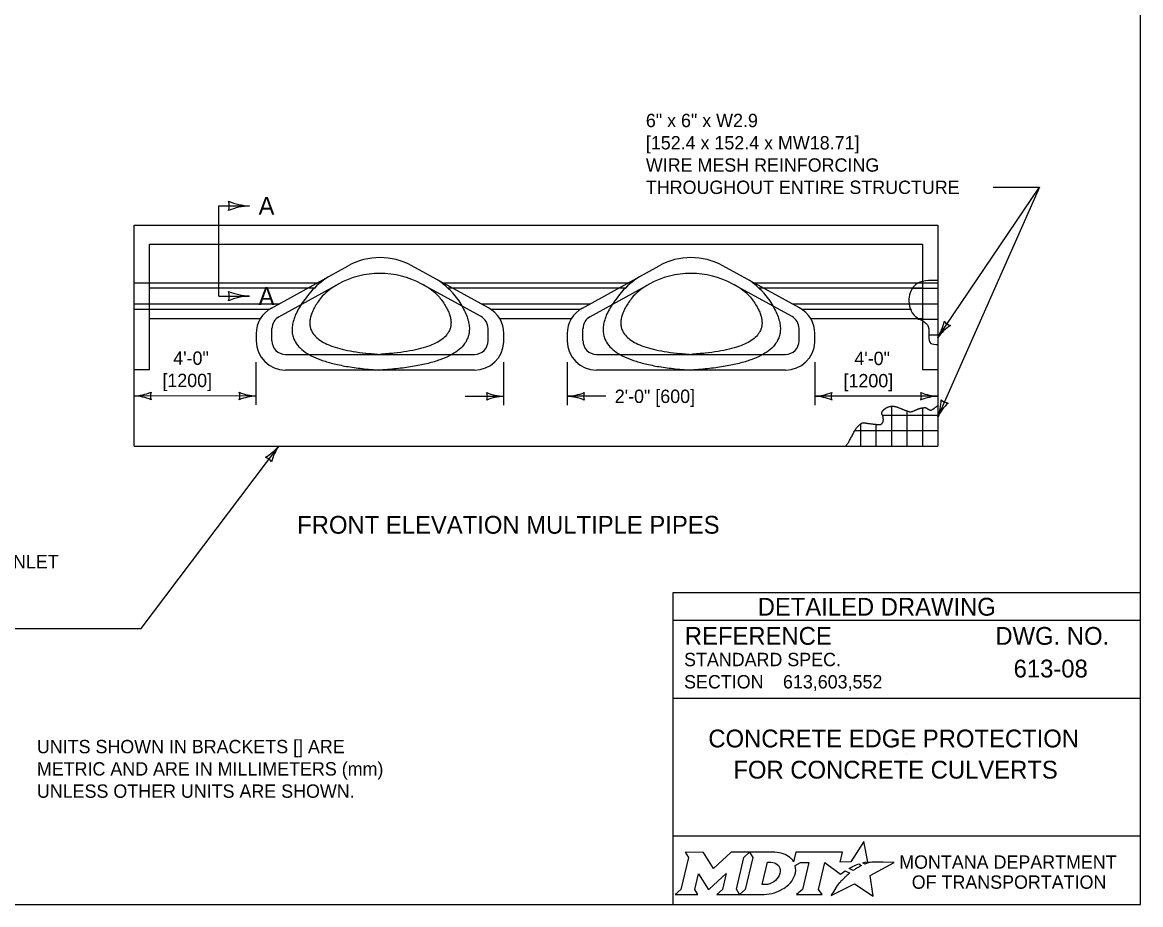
# Model space of a CAD drawing. Extents: x 49991.4 to 50021, y 49987.6 to 50011.4.
# Drawn here: x 50015.92 to 50020.94, y 49999.89 to 50003.85 of the extents above; entities that cross this region are included whole.
import ezdxf

# ---------------------------------------------------------------- set-up
doc = ezdxf.new("R2010")
doc.units = 0
for name, color, linetype in [('Default', 7, 'Continuous'), ('Level 1', 7, 'Continuous'), ('Level 2', 7, 'Continuous'), ('Level 3', 7, 'Continuous'), ('Level 4', 7, 'Continuous'), ('Level 6', 7, 'Continuous')]:
    doc.layers.add(name, color=color, linetype=linetype)

msp = doc.modelspace()

# ---------------------------------------------------------------- linework, layer by layer
at = {"layer": 'Default'}
for points in [[(50019.7003, 50000.0679), (50019.69, 50000.0735), (50019.7016, 50000.0763), (50019.7132, 50000.0783), (50019.6958, 50000.1684), (50019.6363, 50000.0771), (50019.589, 50000.0764), (50019.5993, 50000.1205), (50019.3901, 50000.1206), (50019.38, 50000.0781), (50019.3742, 50000.0864)], [(50018.8933, 50000.1206), (50018.9074, 50000.0972), (50018.8739, 49999.9539), (50018.8482, 49999.9314), (50018.9498, 49999.9314), (50018.9363, 49999.9542), (50018.9525, 50000.0243), (50018.9962, 49999.9553), (50019.0015, 49999.9553), (50019.0766, 50000.0248), (50019.0602, 49999.9537), (50019.0355, 49999.9317), (50019.1371, 49999.9317), (50019.1233, 49999.955), (50019.1565, 50000.0974)], [(50019.1565, 50000.0974), (50019.1818, 50000.1206), (50019.0994, 50000.1206), (50019.0198, 50000.0476), (50018.9753, 50000.1203), (50018.8933, 50000.1206)], [(50019.2954, 50000.1206), (50019.1818, 50000.1206), (50019.1965, 50000.0977), (50019.1626, 49999.9539), (50019.1371, 49999.9317), (50019.2477, 49999.9317)], [(50019.3194, 50000.0339), (50019.3182, 50000.0258), (50019.315, 50000.0165), (50019.3108, 50000.0083), (50019.3052, 50000.0008), (50019.2987, 49999.9939), (50019.2908, 49999.9876), (50019.2825, 49999.9829), (50019.2734, 49999.979), (50019.2643, 49999.9767), (50019.2551, 49999.9758), (50019.2392, 49999.9758), (50019.2628, 50000.0758), (50019.2788, 50000.0758), (50019.2864, 50000.0752), (50019.294, 50000.0733), (50019.3006, 50000.0703), (50019.3067, 50000.0661), (50019.3115, 50000.0611), (50019.3152, 50000.0551), (50019.3179, 50000.0489), (50019.3195, 50000.0415), (50019.3195, 50000.0385), (50019.3194, 50000.0339)], [(50019.3868, 50000.0615), (50019.4114, 50000.0746), (50019.4483, 50000.0746), (50019.4197, 49999.9541), (50019.3922, 49999.9314), (50019.5084, 49999.9314), (50019.4914, 49999.9543), (50019.5196, 50000.0745), (50019.5909, 50000.0228), (50019.612, 50000.0379), (50019.6317, 50000.027)], [(50019.5759, 49999.9711), (50019.5606, 49999.9467), (50019.5559, 49999.9392), (50019.5501, 49999.9306), (50019.5478, 49999.9263), (50019.6531, 49999.9794), (50019.737, 49999.9243), (50019.7239, 50000.017), (50019.8308, 50000.0754), (50019.7815, 50000.0762), (50019.7514, 50000.0766), (50019.7306, 50000.0769), (50019.7238, 50000.0754), (50019.7189, 50000.0742), (50019.7105, 50000.0719), (50019.7003, 50000.0679)], [(50019.6499, 50000.0403), (50019.6475, 50000.0386), (50019.6292, 50000.0482), (50019.6395, 50000.0539), (50019.6436, 50000.0561), (50019.6522, 50000.0601), (50019.6579, 50000.0627), (50019.6658, 50000.0657), (50019.6731, 50000.0684), (50019.6849, 50000.061), (50019.6809, 50000.0589), (50019.6763, 50000.0564), (50019.6721, 50000.0542), (50019.6671, 50000.0513), (50019.6652, 50000.0502), (50019.6625, 50000.0486), (50019.66, 50000.0472), (50019.6577, 50000.0456), (50019.6551, 50000.0438), (50019.6524, 50000.042), (50019.6499, 50000.0403)], [(50019.5898, 49999.9872), (50019.5898, 49999.9872)], [(50019.2934, 49999.939), (50019.3018, 49999.9416), (50019.3148, 49999.947), (50019.3352, 49999.958)]]:
    msp.add_lwpolyline(points, dxfattribs=at)
for centre, radius, start, end in [((50019.2745, 50000.0595), 0.1183, 300.9103, 339.1383), ((50019.3185, 50000.0422), 0.0709, 339.5329, 15.8582)]:
    msp.add_arc(centre, radius, start, end, dxfattribs=at)
for centre, major_axis, ratio, start_param, end_param in [((50019.2933, 50000.0732), (0.0834, -0.0037), 0.568097, 0.61298, 1.570796), ((50019.3489, 50000.0805), (0.0361, -0.0295), 0.469099, 1.225588, 1.570796), ((50019.6206, 50000.0173), (-0.0112, -0.0097), 0.021651, 3.157348, 6.283185), ((50019.5829, 49999.9791), (-0.00694, -0.00806), 0.008222, 0, 3.137361), ((50019.5996, 49999.9974), (-0.0098, -0.0102), 0.016458, 3.141593, 6.279097), ((50019.248, 50000.08), (0, 0.1484), 0.987302, 3.139398, 3.456847)]:
    msp.add_ellipse(centre, major_axis=major_axis, ratio=ratio, start_param=start_param, end_param=end_param, dxfattribs=at)
at = {"layer": 'Level 1'}
for p, q in [((50016.4192, 50002.9359), (50020.0271, 50002.9359)), ((50016.4192, 50001.9446), (50016.4192, 50002.9359)), ((50020.0271, 50002.9359), (50020.0271, 50001.9446)), ((50017.0353, 50002.564), (50017.3799, 50002.7539)), ((50018.0107, 50002.5649), (50017.6657, 50002.7541)), ((50018.4316, 50002.564), (50018.7762, 50002.7539)), ((50019.407, 50002.5649), (50019.062, 50002.7541)), ((50019.9578, 50002.6833), (50019.9578, 50002.5007)), ((50017.0694, 50002.5252), (50017.335, 50002.6714)), ((50017.9766, 50002.5258), (50017.7105, 50002.6718)), ((50018.4657, 50002.5252), (50018.7313, 50002.6714)), ((50019.3729, 50002.5258), (50019.1068, 50002.6718)), ((50019.9159, 50002.6527), (50020.0271, 50002.6527)), ((50016.4192, 50002.5833), (50017.0703, 50002.5833)), ((50017.9771, 50002.5833), (50018.4666, 50002.5833)), ((50019.3734, 50002.5833), (50020.0271, 50002.5833)), ((50016.4192, 50002.5586), (50017.0263, 50002.5586)), ((50018.021, 50002.5586), (50018.4226, 50002.5586)), ((50019.4173, 50002.5586), (50019.9091, 50002.5586)), ((50019.9381, 50002.5139), (50020.0271, 50002.5139)), ((50016.9672, 50002.4488), (50016.9672, 50002.4169)), ((50017.038, 50002.4169), (50017.038, 50002.472)), ((50018.0081, 50002.4169), (50018.0081, 50002.4727)), ((50018.0788, 50002.4114), (50018.0789, 50002.4496)), ((50018.3635, 50002.4488), (50018.3635, 50002.4169)), ((50018.4343, 50002.4169), (50018.4343, 50002.472)), ((50019.4044, 50002.4169), (50019.4044, 50002.4727)), ((50019.4751, 50002.4114), (50019.4752, 50002.4496)), ((50019.9872, 50002.4445), (50020.0271, 50002.4445)), ((50017.0987, 50002.3562), (50017.9474, 50002.3562)), ((50018.495, 50002.3562), (50019.3437, 50002.3562)), ((50017.9474, 50002.2854), (50017.0987, 50002.2854)), ((50019.3437, 50002.2854), (50018.495, 50002.2854)), ((50019.819, 50002.1233), (50019.819, 50001.9446)), ((50019.7784, 50002.0834), (50020.0271, 50002.0834)), ((50019.8884, 50002.1027), (50019.8884, 50001.9446)), ((50019.9578, 50002.116), (50019.9578, 50001.9446)), ((50019.6802, 50002.0435), (50019.6802, 50001.9446)), ((50019.7496, 50002.0421), (50019.7496, 50001.9446)), ((50019.6548, 50002.014), (50020.0271, 50002.014)), ((50016.4192, 50001.9446), (50020.0271, 50001.9446))]:
    msp.add_line(p, q, dxfattribs=at)
msp.add_lwpolyline([(50020.9378, 50008.1646), (50009.7374, 50008.1646), (50009.7374, 49999.8856), (50020.9378, 49999.8856)], close=True, dxfattribs=at)
for centre, major_axis, start_param, end_param in [((50017.523, 50002.494), (0, 0.2967), 5.781332, 6.786673), ((50018.9193, 50002.494), (0, 0.2967), 5.781332, 6.786673), ((50017.523, 50002.3301), (0, 0.3897), 5.781311, 6.786734), ((50018.9193, 50002.3301), (0, 0.3897), 5.781311, 6.786734), ((50017.4619, 50002.4312), (0, 0.2717), 0.485979, 0.816691), ((50017.5916, 50002.4272), (0, 0.2717), 5.466495, 5.799741), ((50018.8582, 50002.4312), (0, 0.2717), 0.485979, 0.816691), ((50018.9879, 50002.4272), (0, 0.2717), 5.466495, 5.799741), ((50017.0987, 50002.4488), (0, 0.1315), 0.503156, 1.570796), ((50017.0987, 50002.472), (0, 0.0606), 0.503453, 1.570796), ((50017.9474, 50002.4727), (0, 0.0606), 4.712389, 5.781265), ((50017.9474, 50002.4496), (0, 0.1315), 4.712389, 5.781202), ((50018.495, 50002.4488), (0, 0.1315), 0.503156, 1.570796), ((50018.495, 50002.472), (0, 0.0606), 0.503453, 1.570796), ((50019.3437, 50002.4727), (0, 0.0606), 4.712389, 5.781265), ((50019.3437, 50002.4496), (0, 0.1315), 4.712389, 5.781202), ((50017.0987, 50002.4169), (0, -0.1315), 4.712389, 6.283185), ((50017.0987, 50002.4169), (0, -0.0606), 4.712389, 6.283185), ((50017.9474, 50002.4169), (0, -0.0606), 0, 1.570796), ((50017.9474, 50002.4169), (0, -0.1315), 0, 1.528873), ((50018.495, 50002.4169), (0, -0.1315), 4.712389, 6.283185), ((50018.495, 50002.4169), (0, -0.0606), 4.712389, 6.283185), ((50019.3437, 50002.4169), (0, -0.0606), 0, 1.570796), ((50019.3437, 50002.4169), (0, -0.1315), 0, 1.528873)]:
    msp.add_ellipse(centre, major_axis=major_axis, ratio=0.999965, start_param=start_param, end_param=end_param, dxfattribs=at)
msp.add_spline([(50020.0271, 50002.6879), (50019.9266, 50002.6683), (50019.8977, 50002.6046), (50019.9266, 50002.5268), (50019.9845, 50002.4806), (50019.9961, 50002.4056), (50020.0271, 50002.4005)], degree=3, dxfattribs=at)
for points, degree in [([(50017.2638, 50002.6173), (50017.0752, 50002.3841), (50017.523, 50002.3562)], 2), ([(50017.7896, 50002.6132), (50017.9707, 50002.384), (50017.523, 50002.3562)], 2), ([(50018.6601, 50002.6173), (50018.4715, 50002.3841), (50018.9193, 50002.3562)], 2), ([(50019.1859, 50002.6132), (50019.367, 50002.384), (50018.9193, 50002.3562)], 2), ([(50019.6132, 50001.9446), (50019.6163, 50001.9477), (50019.6191, 50001.9512), (50019.6218, 50001.9547), (50019.6246, 50001.9583), (50019.6271, 50001.962), (50019.6293, 50001.966), (50019.6336, 50001.9741), (50019.6379, 50001.9823), (50019.6422, 50001.9905), (50019.6465, 50001.9987), (50019.6509, 50002.0069), (50019.6553, 50002.015), (50019.6586, 50002.0211), (50019.6629, 50002.0264), (50019.6674, 50002.0317), (50019.6689, 50002.0334), (50019.6704, 50002.035), (50019.6721, 50002.0366), (50019.6741, 50002.0385), (50019.6762, 50002.0404), (50019.6784, 50002.0421), (50019.6807, 50002.044), (50019.683, 50002.0454), (50019.6856, 50002.0469), (50019.688, 50002.0482), (50019.6904, 50002.0496), (50019.693, 50002.0494), (50019.6973, 50002.049), (50019.7016, 50002.0483), (50019.7059, 50002.0477), (50019.7081, 50002.0473), (50019.7103, 50002.047), (50019.7124, 50002.0466), (50019.7146, 50002.0463), (50019.7167, 50002.046), (50019.7189, 50002.0457), (50019.7263, 50002.0447), (50019.7337, 50002.0439), (50019.7411, 50002.043), (50019.7485, 50002.0421), (50019.756, 50002.0414), (50019.7634, 50002.0408), (50019.7647, 50002.0407), (50019.7661, 50002.0408), (50019.7674, 50002.041), (50019.7688, 50002.0412), (50019.7701, 50002.0417), (50019.7713, 50002.0423), (50019.7726, 50002.043), (50019.7738, 50002.0437), (50019.7749, 50002.0447), (50019.7755, 50002.0452), (50019.7761, 50002.0457), (50019.7766, 50002.0463), (50019.7769, 50002.0465), (50019.7771, 50002.0468), (50019.7774, 50002.0471), (50019.7777, 50002.0475), (50019.7779, 50002.0478), (50019.7782, 50002.0481), (50019.7797, 50002.05), (50019.7808, 50002.0521), (50019.7816, 50002.0545), (50019.7824, 50002.0567), (50019.7827, 50002.0588), (50019.7827, 50002.061), (50019.7827, 50002.0632), (50019.7827, 50002.0654), (50019.7825, 50002.0676), (50019.7824, 50002.0687), (50019.7823, 50002.0697), (50019.7822, 50002.0708), (50019.7821, 50002.0719), (50019.782, 50002.0729), (50019.7819, 50002.074), (50019.7817, 50002.0758), (50019.7812, 50002.0776), (50019.7805, 50002.0793), (50019.7797, 50002.0811), (50019.7787, 50002.0827), (50019.7779, 50002.0845), (50019.7771, 50002.0862), (50019.7764, 50002.0879), (50019.7758, 50002.0897), (50019.7755, 50002.0906), (50019.7754, 50002.0915), (50019.7754, 50002.0923), (50019.7753, 50002.0932), (50019.7754, 50002.094), (50019.7757, 50002.0949), (50019.7765, 50002.0973), (50019.7775, 50002.0995), (50019.7791, 50002.1014), (50019.7808, 50002.1035), (50019.7825, 50002.1054), (50019.7844, 50002.1072), (50019.7854, 50002.1082), (50019.7865, 50002.1092), (50019.7876, 50002.1102), (50019.7886, 50002.1111), (50019.7897, 50002.112), (50019.7908, 50002.1128), (50019.7919, 50002.1137), (50019.793, 50002.1144), (50019.7942, 50002.1151), (50019.7954, 50002.1158), (50019.7967, 50002.1165), (50019.798, 50002.1171), (50019.7995, 50002.1178), (50019.8011, 50002.1185), (50019.8027, 50002.1191), (50019.8074, 50002.1209), (50019.8122, 50002.1221), (50019.8172, 50002.123), (50019.8204, 50002.1236), (50019.8237, 50002.1237), (50019.8269, 50002.1235), (50019.8301, 50002.1233), (50019.8332, 50002.1229), (50019.8363, 50002.122), (50019.8408, 50002.1207), (50019.8452, 50002.1193), (50019.8496, 50002.1176), (50019.854, 50002.1159), (50019.8584, 50002.1141), (50019.8628, 50002.1124), (50019.8672, 50002.1107), (50019.8716, 50002.1088), (50019.876, 50002.1071), (50019.8804, 50002.1054), (50019.8849, 50002.1039), (50019.8894, 50002.1023), (50019.8917, 50002.1015), (50019.8939, 50002.1007), (50019.8962, 50002.1), (50019.8973, 50002.0997), (50019.8985, 50002.0994), (50019.8996, 50002.0991), (50019.9002, 50002.099), (50019.9007, 50002.0989), (50019.9013, 50002.0988), (50019.9019, 50002.0987), (50019.9024, 50002.0986), (50019.903, 50002.0986), (50019.9065, 50002.0984), (50019.9101, 50002.0988), (50019.9135, 50002.1), (50019.9172, 50002.1013), (50019.9206, 50002.1027), (50019.924, 50002.1043), (50019.9275, 50002.106), (50019.9309, 50002.1078), (50019.9344, 50002.1095), (50019.9361, 50002.1103), (50019.9379, 50002.111), (50019.9397, 50002.1117), (50019.9414, 50002.1124), (50019.9432, 50002.1129), (50019.945, 50002.1134), (50019.9487, 50002.1143), (50019.9523, 50002.115), (50019.956, 50002.1157), (50019.9597, 50002.1163), (50019.9635, 50002.1169), (50019.9672, 50002.1171), (50019.9701, 50002.1173), (50019.9731, 50002.1164), (50019.9759, 50002.1151), (50019.979, 50002.1135), (50019.9816, 50002.1116), (50019.9846, 50002.11), (50019.9874, 50002.1085), (50019.9902, 50002.1071), (50019.993, 50002.106), (50019.9954, 50002.1052), (50019.9985, 50002.1057), (50020.0006, 50002.1072), (50020.0094, 50002.1135), (50020.0183, 50002.1198), (50020.0271, 50002.1261)], 3)]:
    msp.add_open_spline(points, degree=degree, dxfattribs=at)
at = {"layer": 'Level 3'}
for p, q in [((50020.0271, 50002.4321), (50020.4835, 50003.1063)), ((50020.4835, 50003.1063), (50020.0271, 50002.0751)), ((50020.2756, 50003.1063), (50020.4835, 50003.1063)), ((50016.9672, 50002.1292), (50016.9672, 50002.3212)), ((50018.0788, 50002.1279), (50018.0788, 50002.3212)), ((50018.3635, 50002.3212), (50018.3635, 50002.1279)), ((50019.4751, 50002.3212), (50019.4751, 50002.1281)), ((50016.9672, 50002.1692), (50016.4192, 50002.1695)), ((50017.9054, 50002.1679), (50018.0788, 50002.1679)), ((50018.5369, 50002.1679), (50018.3635, 50002.1679)), ((50020.0271, 50002.1681), (50019.4751, 50002.1681)), ((50016.4513, 50001.1251), (50017.0684, 50001.9446)), ((50015.8224, 50001.1251), (50016.4513, 50001.1251))]:
    msp.add_line(p, q, dxfattribs=at)
for centre, radius, start, end in [((50016.9492, 50003.3006), 0.2779, 247.456, 267.6395), ((50016.7775, 50003.0229), 0.0685, 342.1388, 17.8612), ((50016.9522, 50002.732), 0.2912, 92.8273, 112.0772), ((50016.9492, 50002.8957), 0.2779, 247.456, 267.6395), ((50016.7775, 50002.618), 0.0685, 342.1388, 17.8612), ((50016.9522, 50002.3271), 0.2912, 92.8273, 112.0772), ((50019.8279, 50002.553), 0.233, 328.733, 347.9829), ((50020.2059, 50002.3), 0.2223, 123.3617, 143.5452), ((50020.099, 50002.5383), 0.0548, 218.0445, 253.7669), ((50016.4077, 50002.4022), 0.233, 272.8273, 292.0772), ((50016.5474, 50002.1695), 0.0548, 162.1388, 197.8612), ((50016.9764, 50002.3913), 0.2223, 247.456, 267.6395), ((50016.839, 50002.1692), 0.0548, 342.1388, 17.8612), ((50018.088, 50002.39), 0.2223, 247.456, 267.6395), ((50017.9506, 50002.1679), 0.0548, 342.1388, 17.8612), ((50018.352, 50002.4006), 0.233, 272.8273, 292.0772), ((50018.4917, 50002.1679), 0.0548, 162.1388, 197.8612), ((50019.4636, 50002.4008), 0.233, 272.8273, 292.0772), ((50019.6033, 50002.1681), 0.0548, 162.1388, 197.8612), ((50020.0363, 50002.3902), 0.2223, 247.456, 267.6395), ((50019.8989, 50002.1681), 0.0548, 342.1388, 17.8612), ((50016.41, 50001.9474), 0.2223, 67.456, 87.6395), ((50016.9787, 50001.9365), 0.233, 92.8273, 112.0772), ((50018.0903, 50001.9352), 0.233, 92.8273, 112.0772), ((50018.3543, 50001.9458), 0.2223, 67.456, 87.6395), ((50019.4659, 50001.946), 0.2223, 67.456, 87.6395), ((50020.0386, 50001.9354), 0.233, 92.8273, 112.0772), ((50019.8096, 50002.1588), 0.233, 338.9544, 358.2042), ((50020.2265, 50001.9768), 0.2223, 133.5831, 153.7666), ((50020.079, 50002.1923), 0.0548, 228.2659, 263.9883), ((50016.8964, 50002.0855), 0.2223, 300.4807, 320.6642), ((50017.2612, 50001.8138), 0.233, 145.852, 165.1018), ((50016.9913, 50001.8422), 0.0548, 35.1635, 70.8858)]:
    msp.add_arc(centre, radius, start, end, dxfattribs=at)
at = {"layer": 'Level 4'}
for p, q in [((50016.4885, 50002.8504), (50019.9578, 50002.8504)), ((50016.4885, 50002.2884), (50016.4885, 50002.8504)), ((50019.9578, 50002.8504), (50019.9578, 50002.2883)), ((50016.4192, 50002.6775), (50017.2544, 50002.6775)), ((50017.7997, 50002.6775), (50018.6507, 50002.6775)), ((50019.196, 50002.6775), (50020.0271, 50002.6775)), ((50016.4885, 50002.6543), (50017.2289, 50002.6543)), ((50017.8271, 50002.6543), (50018.6252, 50002.6543)), ((50019.2234, 50002.6543), (50019.9578, 50002.6543)), ((50016.4885, 50002.517), (50016.9862, 50002.517)), ((50018.0603, 50002.517), (50018.3825, 50002.517)), ((50019.4566, 50002.517), (50019.9578, 50002.517)), ((50016.4192, 50002.2884), (50016.4885, 50002.2884)), ((50019.9578, 50002.2883), (50020.0271, 50002.2883)), ((50020.9378, 50001.2856), (50018.8378, 50001.2856)), ((50018.8378, 50001.2856), (50018.8378, 49999.8856)), ((50020.9378, 50001.1606), (50018.8378, 50001.1606)), ((50020.5739, 50000.9455), (50020.5739, 50000.9455)), ((50019.3321, 50000.8861), (50019.3321, 50000.8861)), ((50020.9378, 50000.8106), (50018.8378, 50000.8106)), ((50019.8878, 50000.5615), (50019.8878, 50000.5615)), ((50020.9378, 50000.1925), (50018.8378, 50000.1925))]:
    msp.add_line(p, q, dxfattribs=at)
for centre, radius, start, end in [((50017.5231, 50002.3564), 0.4187, 123.6589, 138.4291), ((50017.521, 50002.3197), 0.4536, 43.9896, 54.5961), ((50018.9194, 50002.3564), 0.4187, 123.6589, 138.4291), ((50018.9173, 50002.3197), 0.4536, 43.9896, 54.5961)]:
    msp.add_arc(centre, radius, start, end, dxfattribs=at)
for points in [[(50017.2098, 50002.6342), (50016.9488, 50002.3236), (50017.5225, 50002.2854)], [(50017.8473, 50002.6347), (50018.099, 50002.3236), (50017.5259, 50002.2854)], [(50018.6061, 50002.6342), (50018.3451, 50002.3236), (50018.9188, 50002.2854)], [(50019.2436, 50002.6347), (50019.4953, 50002.3236), (50018.9222, 50002.2854)]]:
    msp.add_open_spline(points, degree=2, dxfattribs=at)
at = {"layer": 'Level 6'}
for p, q in [((50016.8, 50002.618), (50016.8, 50003.0229)), ((50016.8, 50003.0229), (50016.9378, 50003.0229)), ((50016.8, 50002.618), (50016.9378, 50002.618))]:
    msp.add_line(p, q, dxfattribs=at)

# ---------------------------------------------------------------- texts
at = {"layer": 'Default'}
for s, p in [('MONTANA DEPARTMENT', (50019.854, 50000.0468)), ('OF TRANSPORTATION', (50019.9102, 49999.9568))]:
    msp.add_text(s, height=0.06, dxfattribs=at).set_placement(p)
at = {"layer": 'Level 2'}
for s, height, p in [('6" x 6" x W2.9', 0.06, (50018.7166, 50003.3763)), ('[152.4 x 152.4 x MW18.71]', 0.06, (50018.7166, 50003.2763)), ('WIRE MESH REINFORCING ', 0.06, (50018.7166, 50003.1763)), ('THROUGHOUT ENTIRE STRUCTURE', 0.06, (50018.7166, 50003.0763)), ('A', 0.08, (50016.9778, 50002.9829)), ('A', 0.08, (50016.9778, 50002.578)), ('4\'-0"', 0.06, (50016.5947, 50002.3093)), ('4\'-0"', 0.06, (50019.6526, 50002.3081)), ('[1200]', 0.06, (50016.546, 50002.2093)), ('[1200]', 0.06, (50019.6039, 50002.2081)), ('2\'-0" [600]', 0.06, (50018.5769, 50002.1379)), ('FRONT ELEVATION MULTIPLE PIPES', 0.08, (50017.1512, 50001.551)), ('CONCRETE CUTOFF WALL INLET', 0.06, (50014.7923, 50001.3954)), ('613-08', 0.08, (50020.3675, 50000.9055)), ('613,603,552', 0.06, (50019.3321, 50000.8561)), ('CONCRETE EDGE PROTECTION', 0.08, (50018.997, 50000.5915)), ('UNITS SHOWN IN BRACKETS [] ARE ', 0.06, (50015.9826, 50000.5652)), ('METRIC AND ARE IN MILLIMETERS (mm) ', 0.06, (50015.9826, 50000.4652)), ('FOR CONCRETE CULVERTS', 0.08, (50019.1095, 50000.4515)), ('UNLESS OTHER UNITS ARE SHOWN.', 0.06, (50015.9826, 50000.3652))]:
    msp.add_text(s, height=height, dxfattribs=at).set_placement(p)
at = {"layer": 'Level 4'}
for s, height, p in [('DETAILED DRAWING', 0.0799, (50019.2188, 50001.1831)), ('REFERENCE', 0.08, (50018.8914, 50001.0522)), ('DWG. NO.', 0.08, (50020.2856, 50001.0522)), ('STANDARD SPEC.', 0.06, (50018.8881, 50000.9562)), ('SECTION', 0.06, (50018.8881, 50000.8562))]:
    msp.add_text(s, height=height, dxfattribs=at).set_placement(p)

doc.saveas('drawing.dxf')
